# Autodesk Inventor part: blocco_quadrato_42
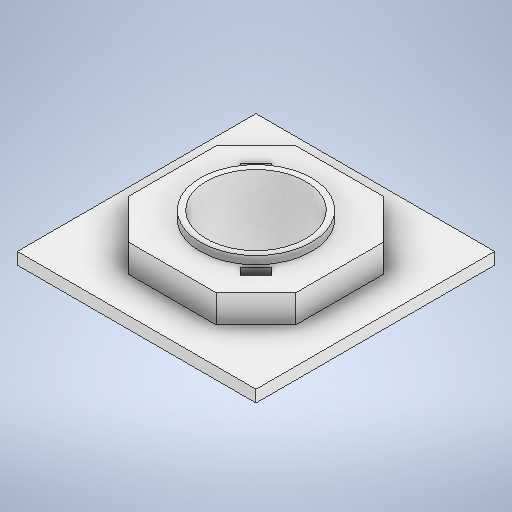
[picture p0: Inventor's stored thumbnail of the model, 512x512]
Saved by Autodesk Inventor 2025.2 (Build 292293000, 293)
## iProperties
Created: 2025-05
Part Number: blocco_quadrato_42
Material: Plastica ABS
Document SubType Name: Modeling
Designer: R5800u
Density: 1.06 g/cm^3
Appearance: Liscia - Bianco
Author: R5800u
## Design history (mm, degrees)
sketch "Schizzo1"
  geometry: L1 (21, 21)-(-21, 21); L2 (-21, 21)-(-21, -21); L3 (-21, -21)-(21, -21); L4 (21, -21)-(21, 21); L5 (21, 21)-(-21, -21); L6 (-21, 21)-(21, -21); 1 further point
  constraints: 12 end point, 2 midpoint, 2 parallel, 1 horizontal, 1 perpendicular
  dimensions: "d0" = 42 distance of L3.end L2.end; "d1" = 42 distance of L2.end L1.end
extrude "Estrusione1" new body sketch "Schizzo1" distance "d2" = 8; taper "d3" = 0 deg
sketch "Schizzo2"
  geometry: C1 r 12.5 at (0, 0); 1 further point
  constraints: 1 centre point, 1 coincident
  dimensions: "d4" = 25 diameter of C1
extrude "Estrusione2" cut sketch "Schizzo2" extent not by distance; stored distance "d5" = 0; taper "d6" = 0 deg
sketch "Schizzo6"
  geometry: L1 (21, -21)-(21, 21) reference; L2 (21, 21)-(-21, 21) reference; L3 (-21, 21)-(-21, -21) reference; L4 (-21, -21)-(21, -21) reference; L5 (-21, -21)-(21, -21); L6 (21, -21)-(21, 21); L7 (21, 21)-(-21, 21); L8 (-21, 21)-(-21, -21); L9 (-21, -21)-(21, 21); L10 (21, -21)-(-21, 21); L11 (-30, 30)-(30, 30); L12 (30, 30)-(30, -30); L13 (30, -30)-(-30, -30); L14 (-30, -30)-(-30, 30); L15 (-30, 30)-(30, -30); L16 (30, 30)-(-30, -30); C1 r 12.5 at (0, 0) reference; C2 r 30 at (0, 0); C3 r 12.5 at (0, 0) reference; A1 r 29.698 centre (0, 0) between (21, -21) and (-21, -21); 9 further points
  constraints: 24 end point, 4 midpoint, 4 parallel, 2 centre point, 2 coincident, 2 horizontal, 2 perpendicular, 1 point on circle, 1 vertical alignment, 1 other
  dimensions: "d18" = 60 diameter of C2; "d54" = 42 distance of L7.end L6.end; "d55" = 42 distance of L5.end L6.end; "d82" = 60 distance of L12.end L13.end; "d83" = 60 distance of L11.end L12.end
extrude "Estrusione5" join sketch "Schizzo6" distance "d13" = 3; taper "d14" = 0 deg
sketch "Schizzo8"
  geometry: L1 (21, -21)-(21, 21) reference; L2 (21, 21)-(-21, 21) reference; L3 (-21, 21)-(-21, -21) reference; L4 (-21, -21)-(21, -21) reference; L5 (-21, -21)-(21, -21); L6 (21, -21)-(21, 21); L7 (21, 21)-(-21, 21); L8 (-21, 21)-(-21, -21); L9 (-21, -21)-(21, 21); L10 (21, -21)-(-21, 21); C1 r 12.5 at (0, 0) reference; 1 further point
  constraints: 12 end point, 2 midpoint, 2 parallel, 1 horizontal, 1 perpendicular
  dimensions: "d56" = 42 distance of L7.end L6.end; "d57" = 42 distance of L6.end L5.end
extrude "Estrusione6" join sketch "Schizzo8" distance "d34" = 10; taper "d35" = 0 deg
chamfer "Smusso3" distance "d36" = 10; stored, may be unused: second distance "d37" = 2, angle "d38" = 45 deg
sketch "Schizzo9"
  geometry: L1 (2.8, -17.2)-(-2.8, -17.2); L2 (-2.8, -17.2)-(-2.8, -14.8); L3 (-2.8, -14.8)-(2.8, -14.8); L4 (2.8, -14.8)-(2.8, -17.2); L5 (2.8, -17.2)-(-2.8, -14.8); L6 (-2.8, -17.2)-(2.8, -14.8); L7 (14.142, -10.182)-(10.182, -14.142); L8 (10.182, -14.142)-(8.485, -12.445); L9 (8.485, -12.445)-(12.445, -8.485); L10 (12.445, -8.485)-(14.142, -10.182); L11 (14.142, -10.182)-(8.485, -12.445); L12 (10.182, -14.142)-(12.445, -8.485); L13 (17.2, 2.8)-(17.2, -2.8); L14 (17.2, -2.8)-(14.8, -2.8); L15 (14.8, -2.8)-(14.8, 2.8); L16 (14.8, 2.8)-(17.2, 2.8); L17 (17.2, 2.8)-(14.8, -2.8); L18 (17.2, -2.8)-(14.8, 2.8); L19 (10.182, 14.142)-(14.142, 10.182); L20 (14.142, 10.182)-(12.445, 8.485); L21 (12.445, 8.485)-(8.485, 12.445); L22 (8.485, 12.445)-(10.182, 14.142); L23 (10.182, 14.142)-(12.445, 8.485); L24 (14.142, 10.182)-(8.485, 12.445); L25 (-2.8, 17.2)-(2.8, 17.2); L26 (2.8, 17.2)-(2.8, 14.8); L27 (2.8, 14.8)-(-2.8, 14.8); L28 (-2.8, 14.8)-(-2.8, 17.2); L29 (-2.8, 17.2)-(2.8, 14.8); L30 (2.8, 17.2)-(-2.8, 14.8); L31 (-14.142, 10.182)-(-10.182, 14.142); L32 (-10.182, 14.142)-(-8.485, 12.445); L33 (-8.485, 12.445)-(-12.445, 8.485); L34 (-12.445, 8.485)-(-14.142, 10.182); L35 (-14.142, 10.182)-(-8.485, 12.445); L36 (-10.182, 14.142)-(-12.445, 8.485); L37 (-17.2, -2.8)-(-17.2, 2.8); L38 (-17.2, 2.8)-(-14.8, 2.8); L39 (-14.8, 2.8)-(-14.8, -2.8); L40 (-14.8, -2.8)-(-17.2, -2.8); L41 (-17.2, -2.8)-(-14.8, 2.8); L42 (-17.2, 2.8)-(-14.8, -2.8); L43 (-10.182, -14.142)-(-14.142, -10.182); L44 (-14.142, -10.182)-(-12.445, -8.485); L45 (-12.445, -8.485)-(-8.485, -12.445); L46 (-8.485, -12.445)-(-10.182, -14.142); L47 (-10.182, -14.142)-(-12.445, -8.485); L48 (-14.142, -10.182)-(-8.485, -12.445); C1 r 12.5 at (0, 0) reference; 9 further points
  constraints: 96 end point, 2 midpoint, 2 parallel, 1 horizontal, 1 perpendicular, 89 other
  dimensions: "d39" = 5.6 distance of L2.end L3.end; "d40" = 2.4 distance of L1.end L2.end; "d41" = 16 distance of C1.centre point (0, -16); "d60" = 360 deg dimension on point (0, 0) L1.start (derived)
extrude "Estrusione7" cut sketch "Schizzo9" distance "d42" = 7; taper "d43" = 0 deg
sketch "Schizzo13"
  geometry: L1 (14.142, 7)-(0, 7) reference; L2 (0, 7)-(0, 0) reference; L3 (0, 0)-(14.142, 0) reference; L4 (14.142, 0)-(14.142, 7) reference; L5 (0, 0)-(-15.556, 0) reference; L6 (14.142, 7)-(0, 0); L7 (0, 0)-(0, 7); L8 (0, 0)-(14.142, 0) reference; L9 (0, 7)-(14.142, 0); 2 further points
  constraints: 6 end point, 1 collinear, 1 midpoint
hole "Foro4" sketch "Schizzo13" at (7.071, 3.5) diameter "d69" = 3.4; stored, may be unused: countersink angle "d73" = 90 deg, drill point angle "d75" = 0 deg; dims "d70" = 6, "d71" = 5.5, "d72" = 3, "d74" = 8
sketch "Schizzo14"
  geometry: C1 r 14 at (0, 0); C2 r 12.5 at (0, 0) reference; 1 further point
  constraints: 1 centre point, 1 coincident
  dimensions: "d76" = 28 diameter of C1
extrude "Estrusione9" join sketch "Schizzo14" distance "d77" = 2; taper "d78" = 0 deg
sketch "Schizzo17"
  geometry: L1 (10.304, 3.5)-(8.688, 0.7); L2 (8.688, 0.7)-(5.454, 0.7); L3 (5.454, 0.7)-(3.838, 3.5); L4 (3.838, 3.5)-(5.454, 6.3); L5 (5.454, 6.3)-(8.688, 6.3); L6 (8.688, 6.3)-(10.304, 3.5); C1 r 1.7 at (7.071, 3.5) reference; 2 further points
  constraints: 12 end point, 1 coincident, 13 other
  dimensions: "d79" = 5.6 distance between parallel lines of L5 L2
extrude "Estrusione10" cut sketch "Schizzo17" distance "d80" = 3; taper "d81" = 0 deg
node "Solido1"
node "Linea chiusa proiettata2"
node "Linea chiusa proiettata3"
node "Schizzo - Serie circolare1" dims "d60" = 360 deg (derived)
node "Linea chiusa proiettata5"
